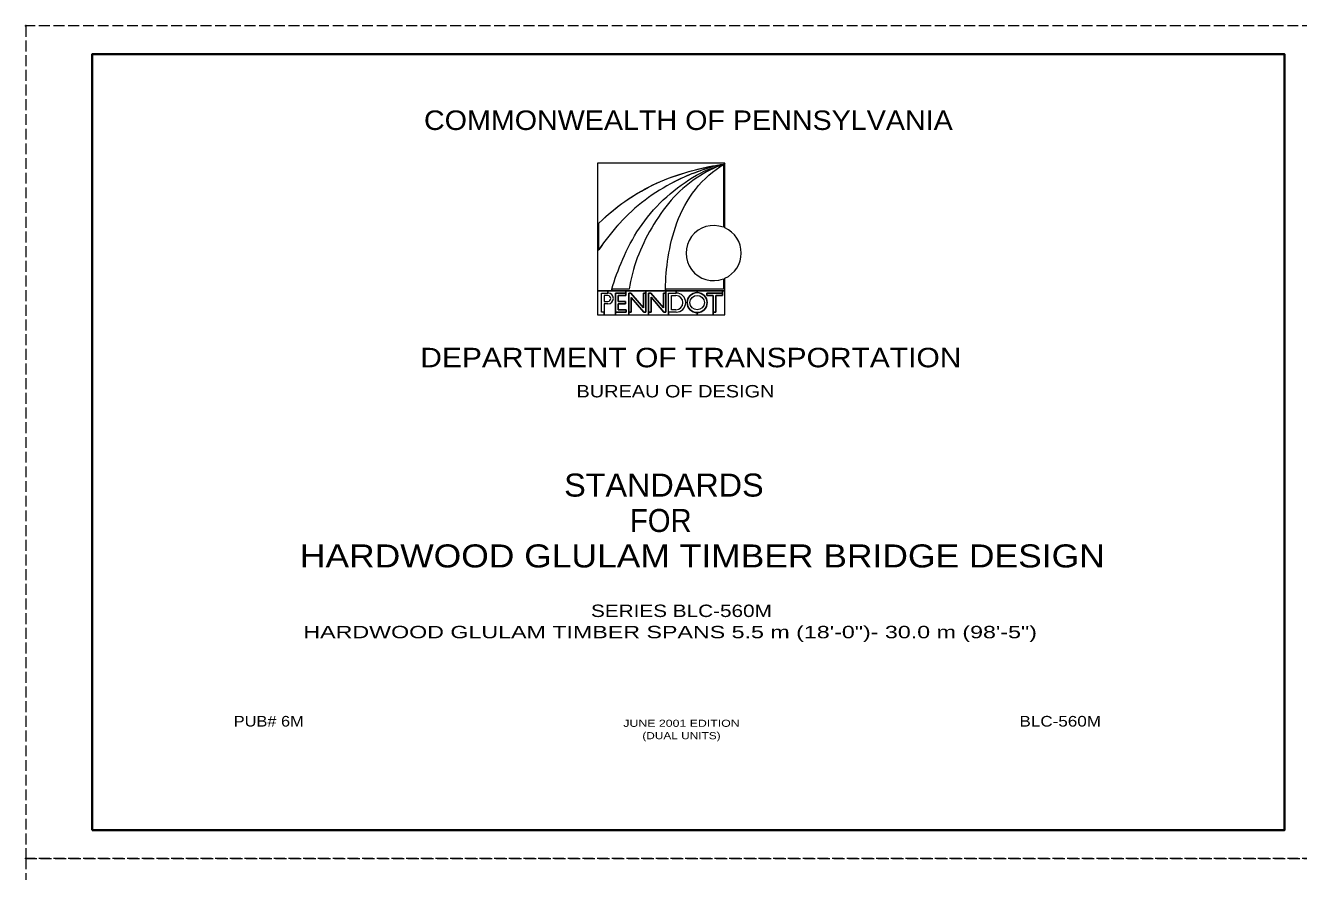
# Model space of a CAD drawing. Extents: x 0 to 68, y -44 to 0.
# Drawn here: x -0.01 to 33.62, y -22.35 to 0.01 of the extents above; entities that cross this region are included whole.
import ezdxf
from ezdxf.enums import TextEntityAlignment as Align

# ---------------------------------------------------------------- set-up
doc = ezdxf.new("R2010")
doc.units = 0
doc.header["$LTSCALE"] = 0.048
doc.header["$PDMODE"] = 32
doc.header["$PDSIZE"] = 0.024
doc.linetypes.add('LONG_DASHED', pattern=[7.5, 6, -1.5])
for name, color, linetype, lineweight in [('1', 7, 'Continuous', 25), ('4', 7, 'Continuous', 35), ('63', 7, 'LONG_DASHED', 13), ('9', 7, 'Continuous', 13)]:
    doc.layers.add(name, color=color, linetype=linetype, lineweight=lineweight)
doc.layers.add('62', color=7, linetype='Continuous')

msp = doc.modelspace()

# ---------------------------------------------------------------- linework, layer by layer
at = {"layer": '1', "lineweight": 35}
msp.add_lwpolyline([(1.75, -21.25), (33.25, -21.25), (33.25, -0.75), (1.75, -0.75)], close=True, dxfattribs=at)
at = {"layer": '62'}
for p in [(0, 0), (0, -22)]:
    msp.add_point(p, dxfattribs=at)
at = {"layer": '63'}
for points in [[(0, -22), (34, -22), (34, 0), (0, 0)], [(0, -44), (34, -44), (34, -22), (0, -22)]]:
    msp.add_lwpolyline(points, close=True, dxfattribs=at)
at = {"layer": '9'}
for p, q in [((18.46442, -3.629), (15.09542, -3.629)), ((15.13542, -5.91725), (15.13542, -5.21442)), ((15.09542, -5.91725), (15.13542, -5.91725)), ((18.46442, -6.99875), (15.09542, -6.99875)), ((15.37567, -6.99875), (15.37567, -7.05842)), ((15.93233, -6.95875), (15.47942, -6.95875)), ((15.47942, -6.99875), (15.47942, -6.95875)), ((15.47942, -6.99875), (15.47942, -6.95875)), ((15.85192, -6.99875), (15.85192, -7.05842)), ((16.37983, -6.99875), (16.37983, -7.05842)), ((16.89725, -6.99875), (16.89725, -6.95875)), ((16.90808, -6.99875), (16.90808, -7.05842)), ((17.17708, -6.99875), (17.17708, -7.05842)), ((17.73208, -6.99875), (17.73208, -7.04883)), ((18.40117, -6.99875), (18.40117, -7.05842)), ((15.28, -7.2805), (15.37375, -7.2805)), ((15.09542, -7.63883), (18.46442, -7.63883)), ((15.28, -7.63883), (15.28, -7.56525)), ((15.57375, -7.63883), (15.57375, -7.56525)), ((15.92458, -7.63883), (15.92458, -7.56525)), ((16.4495, -7.63883), (16.4495, -7.56525)), ((17.17708, -7.56525), (16.97625, -7.56525)), ((16.97625, -7.63883), (16.97625, -7.56525)), ((17.73208, -7.63883), (17.73208, -7.57767)), ((18.1555, -7.63883), (18.1555, -7.56525))]:
    msp.add_line(p, q, dxfattribs=at)
for points in [[(15.09542, -3.629), (15.09542, -6.99875), (15.09542, -7.63883)], [(18.42442, -3.669), (18.46442, -3.629), (15.09542, -3.629), (15.09542, -5.91725), (15.13542, -5.91725), (15.13542, -5.21442)], [(18.46442, -5.33725), (18.46442, -3.629), (18.42442, -3.669), (18.42442, -5.32083)], [(18.46442, -5.33725), (18.46442, -3.629), (18.42442, -3.669), (18.42442, -5.32083)], [(15.13542, -5.91725), (15.09542, -5.91725), (15.09542, -6.99875), (15.47942, -6.99875)], [(18.42442, -6.6855), (18.42442, -6.95875), (16.89725, -6.95875), (16.89725, -6.99875), (18.46442, -6.99875), (18.46442, -6.66908)], [(18.42442, -6.6855), (18.42442, -6.95875), (16.89725, -6.95875)], [(18.46442, -7.63883), (18.46442, -6.99875), (18.46442, -6.66908)], [(15.28, -7.56525), (15.20775, -7.56525), (15.20775, -7.05842), (15.37567, -7.05842)], [(15.28, -7.63883), (15.57375, -7.63883), (15.57375, -7.56525), (15.57375, -7.05842), (15.85192, -7.05842), (15.85192, -6.99875), (15.37567, -6.99875), (15.37567, -7.05842)], [(15.93233, -6.95875), (15.47942, -6.95875), (15.47942, -6.99875), (16.89725, -6.99875), (16.89725, -6.95875)], [(16.97625, -7.56525), (16.97625, -7.05842), (17.17708, -7.05842)], [(17.17708, -7.56525), (16.97625, -7.56525), (16.97625, -7.05842), (17.17708, -7.05842)], [(17.73208, -7.04883), (17.73208, -6.99875), (17.17708, -6.99875), (17.17708, -7.05842)], [(17.73208, -7.57767), (17.73208, -7.63883), (18.1555, -7.63883), (18.1555, -7.56525), (18.1555, -7.12717), (17.98642, -7.12717), (17.98642, -7.05842), (18.40117, -7.05842), (18.40117, -6.99875), (17.73208, -6.99875), (17.73208, -7.04883)], [(18.40117, -7.05842), (17.98642, -7.05842), (18.40117, -7.05842)], [(15.37375, -7.12717), (15.28, -7.12717), (15.28, -7.2805)], [(15.37567, -7.34525), (15.28, -7.34525), (15.28, -7.56525)], [(15.37567, -7.34525), (15.28, -7.34525), (15.28, -7.56525), (15.28, -7.63883)], [(17.17175, -7.49933), (17.05042, -7.49933), (17.05042, -7.12717), (17.17175, -7.12717)], [(17.17708, -7.56525), (16.97625, -7.56525), (16.97625, -7.63883)], [(16.97625, -7.63883), (17.73208, -7.63883), (17.73208, -7.57767)]]:
    msp.add_lwpolyline(points, dxfattribs=at)
for points in [[(15.28, -7.63883), (15.28, -7.56525), (15.20775, -7.56525), (15.20775, -7.05842), (15.37567, -7.05842), (15.37567, -6.99875), (15.09542, -6.99875), (15.09542, -7.63883)], [(15.64567, -7.49933), (15.8585, -7.49933), (15.8585, -7.56525), (15.57375, -7.56525), (15.57375, -7.63883), (15.92458, -7.63883), (15.92458, -7.56525), (15.92458, -7.05842), (15.9825, -7.05842), (16.31458, -7.44983), (16.31458, -7.05842), (16.37983, -7.05842), (16.37983, -6.99875), (15.85192, -6.99875), (15.85192, -7.05842), (15.85192, -7.12717), (15.64567, -7.12717), (15.64567, -7.2805), (15.84308, -7.2805), (15.84308, -7.34525), (15.64567, -7.34525)], [(15.57375, -7.05842), (15.57375, -7.56525), (15.8585, -7.56525), (15.8585, -7.49933), (15.64567, -7.49933), (15.64567, -7.34525), (15.84308, -7.34525), (15.84308, -7.2805), (15.64567, -7.2805), (15.64567, -7.12717), (15.85192, -7.12717), (15.85192, -7.05842)], [(15.99133, -7.56525), (15.92458, -7.56525), (15.92458, -7.63883), (16.4495, -7.63883), (16.4495, -7.56525), (16.4495, -7.05842), (16.51075, -7.05842), (16.84133, -7.44808), (16.84133, -7.05842), (16.90808, -7.05842), (16.90808, -6.99875), (16.37983, -6.99875), (16.37983, -7.05842), (16.37983, -7.56525), (16.3225, -7.56525), (15.99133, -7.17492)], [(16.31458, -7.44983), (15.9825, -7.05842), (15.92458, -7.05842), (15.92458, -7.56525), (15.99133, -7.56525), (15.99133, -7.17492), (16.3225, -7.56525), (16.37983, -7.56525), (16.37983, -7.05842), (16.31458, -7.05842)], [(16.51625, -7.56525), (16.4495, -7.56525), (16.4495, -7.63883), (16.97625, -7.63883), (16.97625, -7.56525), (16.97625, -7.05842), (17.17708, -7.05842), (17.17708, -6.99875), (16.90808, -6.99875), (16.90808, -7.05842), (16.90808, -7.56525), (16.85067, -7.56525), (16.51625, -7.171)], [(16.84133, -7.44808), (16.51075, -7.05842), (16.4495, -7.05842), (16.4495, -7.56525), (16.51625, -7.56525), (16.51625, -7.171), (16.85067, -7.56525), (16.90808, -7.56525), (16.90808, -7.05842), (16.84133, -7.05842)], [(18.40117, -7.05842), (17.98642, -7.05842), (17.98642, -7.12717), (18.1555, -7.12717), (18.1555, -7.56525), (18.22683, -7.56525), (18.22683, -7.12717), (18.40117, -7.12717)], [(18.22683, -7.56525), (18.1555, -7.56525), (18.1555, -7.63883), (18.46442, -7.63883), (18.46442, -6.99875), (18.40117, -6.99875), (18.40117, -7.05842), (18.40117, -7.12717), (18.22683, -7.12717)]]:
    msp.add_lwpolyline(points, close=True, dxfattribs=at)
for radius in [0.26443, 0.1909]:
    msp.add_circle((17.73208, -7.31326), radius, dxfattribs=at)
for centre, radius, start, end in [((18.16776, -6.00318), 0.72901, 69.38904, 290.61096), ((18.16776, -6.00318), 0.72901, 69.38904, 290.61096), ((18.16776, -6.00318), 0.72901, 294.00959, 65.99041), ((18.16776, -6.00318), 0.72901, 294.00959, 65.99041), ((15.37566, -7.20187), 0.14342, 270.00001, 90), ((15.37566, -7.20187), 0.14342, 270.00001, 90), ((17.17708, -7.31184), 0.25339, 270, 90), ((17.17708, -7.31184), 0.25339, 270, 90), ((17.17708, -7.31184), 0.25339, 270, 90), ((17.73208, -7.31326), 0.26443, 90, 270), ((17.73208, -7.31326), 0.26443, 270, 90), ((15.37372, -7.20385), 0.07667, 270, 90), ((17.17174, -7.31326), 0.18607, 270, 90)]:
    msp.add_arc(centre, radius, start, end, dxfattribs=at)
for points in [[(18.42442, -3.669), (18.31433, -3.66642), (17.85967, -3.79767), (17.13933, -4.09125), (16.33075, -4.58067), (15.66617, -5.19842), (15.29925, -5.66983), (15.13483, -5.91817)], [(15.13483, -5.21508), (15.39083, -4.96217), (15.90817, -4.54358), (16.76467, -4.08117), (17.619, -3.80842), (18.18425, -3.67767), (18.42442, -3.669)], [(18.34433, -3.67375), (18.24742, -3.68608), (17.82725, -3.81083), (17.13933, -4.09125), (16.33075, -4.58067), (15.66642, -5.19817), (15.29967, -5.66933), (15.13542, -5.91725)], [(15.47942, -6.95875), (15.55183, -6.70208), (15.74092, -6.17483), (16.1725, -5.329), (16.81175, -4.575), (17.60675, -3.966), (18.16333, -3.72267), (18.42442, -3.669)], [(15.47942, -6.95875), (15.55183, -6.70208), (15.74092, -6.17483), (16.1725, -5.329), (16.81175, -4.575), (17.60675, -3.966), (18.16333, -3.72267), (18.42442, -3.669)], [(18.42442, -3.669), (18.19992, -3.73092), (17.68975, -3.99617), (17.01525, -4.57592), (16.51183, -5.33067), (16.12058, -6.12258), (15.978, -6.68433), (15.93233, -6.95875)], [(18.42442, -3.669), (18.19992, -3.73092), (17.68975, -3.99617), (17.01525, -4.57592), (16.51183, -5.33067), (16.12058, -6.12258), (15.978, -6.68433), (15.93233, -6.95875)], [(15.96192, -4.54517), (16.22292, -4.37367), (16.76467, -4.08117), (17.58942, -3.81783), (18.124, -3.69175), (18.34433, -3.67375)], [(16.89725, -6.95875), (16.899, -6.67625), (16.94667, -6.12917), (17.15292, -5.19942), (17.6305, -4.28608), (18.17692, -3.81325), (18.42442, -3.669)], [(16.89725, -6.95875), (16.899, -6.67625), (16.94667, -6.12917), (17.15292, -5.19942), (17.6305, -4.28608), (18.17692, -3.81325), (18.42442, -3.669)], [(18.34433, -3.67375), (18.37267, -3.67017), (18.3995, -3.66842), (18.42442, -3.669)], [(18.42442, -3.669), (18.39808, -3.66992), (18.37142, -3.6715), (18.34433, -3.67375)], [(15.13542, -5.21442), (15.39125, -4.96183), (15.666, -4.73958), (15.96192, -4.54517)]]:
    msp.add_open_spline(points, degree=3, dxfattribs=at)

# ---------------------------------------------------------------- texts
at = {"layer": '4'}
for s, height, width, p in [('COMMONWEALTH OF PENNSYLVANIA', 0.5148, 1.1, (17.5, -2.75)), ('DEPARTMENT OF TRANSPORTATION', 0.5148, 1.15, (17.56529, -9.02167)), ('BUREAU OF DESIGN', 0.3276, 1.2, (17.15962, -9.81733)), ('STANDARDS', 0.6084, 1.05, (16.85417, -12.43833)), ('FOR', 0.6084, 0.95, (16.77092, -13.37442)), ('HARDWOOD GLULAM TIMBER BRIDGE DESIGN', 0.6084, 1.15, (17.86867, -14.3105)), ('SERIES BLC-560M', 0.3276, 1.25, (17.31683, -15.621)), ('HARDWOOD GLULAM TIMBER SPANS 5.5 m (18\'-0")- 30.0 m (98\'-5")', 0.3276, 1.4, (17.01921, -16.18258)), ('PUB# 6M', 0.2808, 1.15, (6.41467, -18.51575)), ('JUNE 2001 EDITION', 0.1872, 1.3, (17.31837, -18.52275)), ('BLC-560M', 0.2808, 1.2, (27.32367, -18.51575)), ('(DUAL UNITS)', 0.1872, 1.25, (17.31833, -18.85042))]:
    msp.add_text(s, height=height, dxfattribs=dict(at, width=width)).set_placement(p, align=Align.CENTER)

doc.saveas('drawing.dxf')
